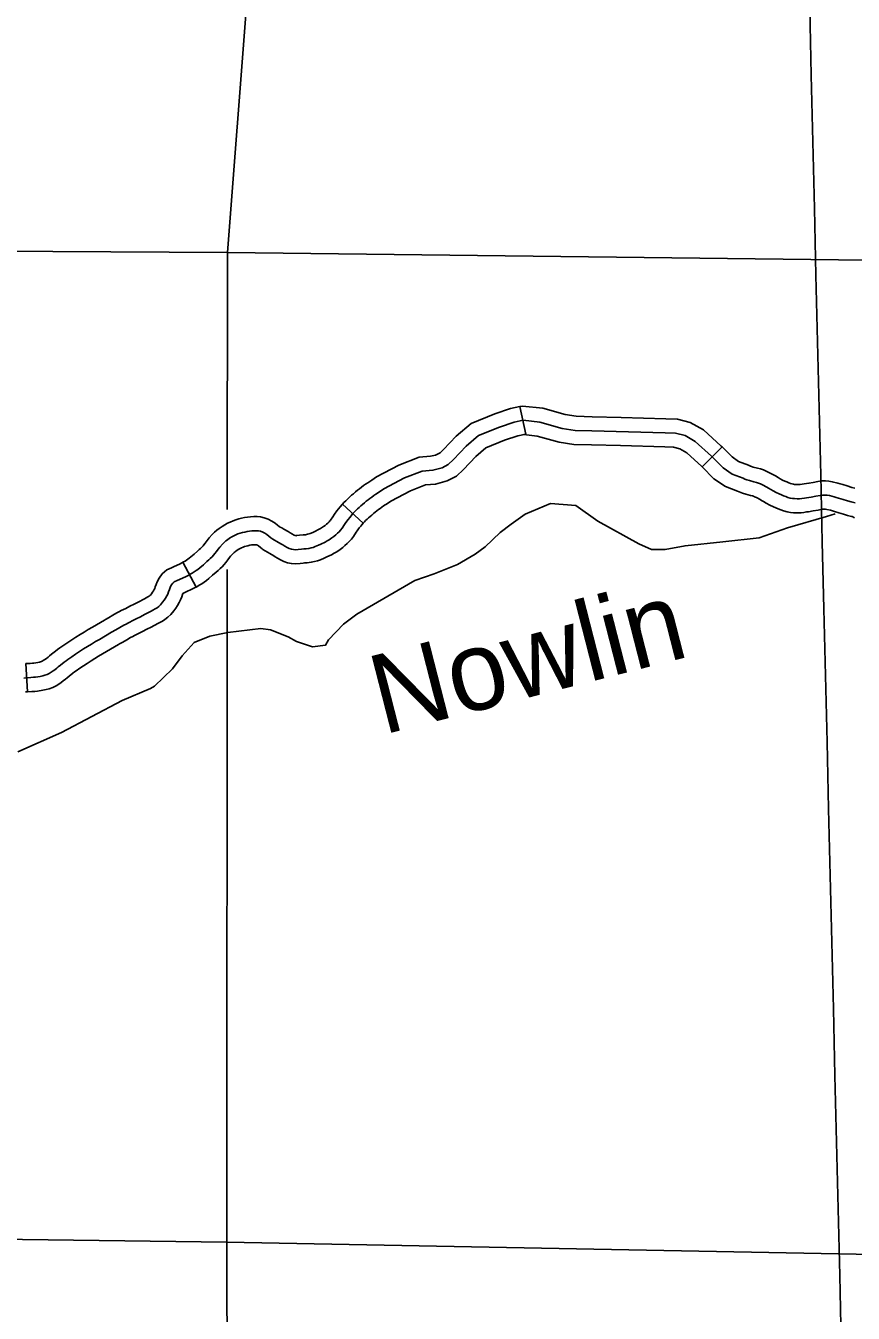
# Model space of a CAD drawing. Extents: x -19 to 366, y -4 to 359.
# Drawn here: x 134.181 to 135.016, y 195.99 to 197.29 of the extents above; entities that cross this region are included whole.
import ezdxf

# ---------------------------------------------------------------- set-up
doc = ezdxf.new("R2010")
doc.units = 0
for name, color, linetype in [('Level 35', 7, 'Continuous'), ('Level 45', 7, 'Continuous'), ('Level 5', 7, 'Continuous'), ('Level 60', 7, 'Continuous')]:
    doc.layers.add(name, color=color, linetype=linetype)

msp = doc.modelspace()

# ---------------------------------------------------------------- linework, layer by layer
at = {"layer": 'Level 35'}
for points in [[(134.5928, 196.7366), (134.6162, 196.7459), (134.6339, 196.7564), (134.644, 196.7637), (134.6594, 196.7782), (134.6702, 196.7867), (134.6845, 196.7967), (134.7101, 196.8075), (134.7355, 196.8055), (134.7579, 196.7898), (134.799, 196.7667), (134.8119, 196.7611), (134.8259, 196.7613), (134.8459, 196.7649), (134.884, 196.769), (134.9206, 196.7728), (134.9493, 196.7829), (134.9885, 196.7943)], [(134.9885, 196.7943), (134.9973, 196.7973)], [(134.1726, 196.557), (134.2167, 196.5764), (134.278, 196.6088), (134.3066, 196.6208), (134.3104, 196.6232), (134.3287, 196.6408), (134.3384, 196.6538), (134.3504, 196.6671), (134.3662, 196.6737), (134.3843, 196.6773), (134.4179, 196.6815), (134.4274, 196.68), (134.4452, 196.673), (134.4536, 196.6682), (134.4699, 196.663), (134.4831, 196.6647), (134.4861, 196.67), (134.5011, 196.6857), (134.5146, 196.6957), (134.5732, 196.73), (134.5928, 196.7366)]]:
    msp.add_lwpolyline(points, dxfattribs=at)
at = {"layer": 'Level 45'}
for p, q in [((134.6792, 196.9054), (134.6851, 196.8776)), ((134.8831, 196.8647), (134.863, 196.8446)), ((134.5002, 196.807), (134.5211, 196.7878)), ((134.3392, 196.7483), (134.3524, 196.7232)), ((134.1806, 196.6459), (134.1822, 196.6175))]:
    msp.add_line(p, q, dxfattribs=at)
for points in [[(134.6792, 196.9054), (134.6696, 196.9034), (134.6538, 196.8982), (134.63, 196.8884), (134.615, 196.8757), (134.6022, 196.862), (134.5986, 196.8587), (134.5953, 196.8569), (134.5939, 196.8565)], [(134.7814, 196.8944), (134.7522, 196.8951), (134.7361, 196.8956), (134.7247, 196.8973), (134.7022, 196.9037), (134.6818, 196.906), (134.6792, 196.9054)], [(134.9043, 196.8332), (134.8933, 196.8373), (134.8841, 196.8436), (134.8724, 196.8553), (134.856, 196.8703), (134.8458, 196.8761), (134.8361, 196.8785), (134.8259, 196.879), (134.7518, 196.8809), (134.7348, 196.8814), (134.7217, 196.8834), (134.6994, 196.8897), (134.6825, 196.8916), (134.6733, 196.8897), (134.6587, 196.8848), (134.6374, 196.8761), (134.6248, 196.8654), (134.6122, 196.8519), (134.6069, 196.847), (134.6006, 196.8436), (134.5914, 196.8412), (134.5807, 196.8402), (134.5628, 196.8334), (134.5418, 196.8223)], [(134.8831, 196.8647), (134.8823, 196.8655), (134.8644, 196.8818), (134.8511, 196.8894), (134.8382, 196.8926), (134.8265, 196.8932), (134.7814, 196.8944)], [(134.6851, 196.8776), (134.677, 196.8759), (134.6637, 196.8715), (134.6449, 196.8638), (134.6347, 196.8551), (134.6222, 196.8418), (134.6152, 196.8353), (134.6058, 196.8303), (134.6011, 196.8291)], [(134.7806, 196.866), (134.7514, 196.8668), (134.7336, 196.8673), (134.7188, 196.8695), (134.6967, 196.8757), (134.6832, 196.8772), (134.6851, 196.8776)], [(134.863, 196.8446), (134.8626, 196.845), (134.8476, 196.8587), (134.8404, 196.8628), (134.834, 196.8644), (134.8254, 196.8648), (134.7806, 196.866)], [(134.5939, 196.8565), (134.5889, 196.8552), (134.5775, 196.8542), (134.5569, 196.8464), (134.5345, 196.8345), (134.5297, 196.8313), (134.5256, 196.8286), (134.5235, 196.8271), (134.5215, 196.8256), (134.5193, 196.8241), (134.5173, 196.8225), (134.5153, 196.8209), (134.5133, 196.8192), (134.5112, 196.8175), (134.5094, 196.8159), (134.5074, 196.8142), (134.5055, 196.8124), (134.5035, 196.8104), (134.5016, 196.8085), (134.5002, 196.807)], [(134.9606, 196.8266), (134.9591, 196.8266), (134.9572, 196.8267), (134.9561, 196.8268), (134.9552, 196.827), (134.9538, 196.8274), (134.9522, 196.8279), (134.9504, 196.8286), (134.9486, 196.8293), (134.9466, 196.8302), (134.9442, 196.8313), (134.9418, 196.8326), (134.9398, 196.8338), (134.9372, 196.8354), (134.935, 196.8366), (134.9305, 196.839), (134.9277, 196.8403), (134.9249, 196.8415), (134.9219, 196.8425), (134.9188, 196.8433), (134.9144, 196.8444), (134.9129, 196.8448), (134.912, 196.8452), (134.9099, 196.8462), (134.8999, 196.85), (134.8932, 196.8546), (134.8831, 196.8647)], [(134.9629, 196.7983), (134.9621, 196.7982), (134.9586, 196.7982), (134.9553, 196.7983), (134.9522, 196.7986), (134.9488, 196.7992), (134.9453, 196.8002), (134.9426, 196.8012), (134.9399, 196.8022), (134.9375, 196.8032), (134.9349, 196.8043), (134.9315, 196.8059), (134.9277, 196.8079), (134.925, 196.8095), (134.923, 196.8107), (134.9216, 196.8115), (134.9178, 196.8136), (134.916, 196.8144), (134.9148, 196.8149), (134.9137, 196.8153), (134.9118, 196.8158), (134.907, 196.8169), (134.9037, 196.8179), (134.9005, 196.8192), (134.8986, 196.8201), (134.8867, 196.8246), (134.875, 196.8326), (134.863, 196.8446)], [(134.6011, 196.8291), (134.5939, 196.8272), (134.5839, 196.8263), (134.5687, 196.8205), (134.549, 196.81), (134.5455, 196.8077), (134.5417, 196.8051), (134.5399, 196.8039), (134.5382, 196.8026), (134.5365, 196.8014), (134.5348, 196.8001), (134.5331, 196.7988), (134.5315, 196.7974), (134.5297, 196.7959), (134.5281, 196.7945), (134.5264, 196.7931), (134.525, 196.7918), (134.5235, 196.7903), (134.5222, 196.789), (134.5211, 196.7878)], [(135.0174, 196.8083), (135.0133, 196.8093), (135.0098, 196.8103), (135.0053, 196.8117), (135.0008, 196.8131), (134.9984, 196.8138), (134.9962, 196.8144), (134.9916, 196.8155), (134.9893, 196.8159), (134.9869, 196.8161), (134.9846, 196.8161), (134.9823, 196.8158), (134.9776, 196.8149), (134.9729, 196.8141), (134.9683, 196.8134), (134.9662, 196.8131), (134.9636, 196.8127), (134.9613, 196.8124), (134.9589, 196.8124), (134.9563, 196.8125), (134.9541, 196.8127), (134.952, 196.8131), (134.9496, 196.8138), (134.9474, 196.8145), (134.9451, 196.8154), (134.943, 196.8163), (134.9408, 196.8173), (134.9378, 196.8186), (134.9348, 196.8202), (134.9324, 196.8217), (134.9301, 196.8231), (134.9283, 196.8241), (134.9241, 196.8263), (134.9218, 196.8273), (134.9198, 196.8282), (134.9178, 196.8289), (134.9153, 196.8296), (134.9107, 196.8307), (134.9083, 196.8314), (134.9062, 196.8322), (134.9043, 196.8332)], [(135.017, 196.823), (135.014, 196.8239), (135.0095, 196.8253), (135.0049, 196.8267), (135.0023, 196.8275), (134.9998, 196.8282), (134.9944, 196.8295), (134.991, 196.83), (134.9876, 196.8303), (134.9836, 196.8303), (134.9799, 196.8298), (134.9751, 196.8289), (134.9707, 196.8281), (134.9661, 196.8274), (134.964, 196.8271), (134.9617, 196.8267), (134.96, 196.8266)], [(134.5418, 196.8223), (134.5376, 196.8195), (134.5337, 196.8169), (134.5317, 196.8155), (134.5298, 196.8141), (134.5279, 196.8127), (134.526, 196.8113), (134.5242, 196.8098), (134.5224, 196.8083), (134.5204, 196.8067), (134.5188, 196.8052), (134.5169, 196.8036), (134.5152, 196.8021), (134.5135, 196.8004), (134.5119, 196.7987), (134.5104, 196.7971), (134.5088, 196.7952), (134.5074, 196.7935), (134.5058, 196.7915), (134.5035, 196.7884), (134.5022, 196.7864), (134.4997, 196.7826), (134.4983, 196.7808), (134.4968, 196.7791), (134.4951, 196.7775), (134.4933, 196.7759), (134.4915, 196.7744), (134.4894, 196.7728), (134.4867, 196.7709), (134.4848, 196.7698), (134.4826, 196.7686), (134.4783, 196.7665), (134.4761, 196.7654), (134.4727, 196.764), (134.4706, 196.7633), (134.4685, 196.7627), (134.4662, 196.7622), (134.4636, 196.7618), (134.4612, 196.7618), (134.4587, 196.7616), (134.4555, 196.7611), (134.453, 196.7608), (134.4508, 196.761), (134.4486, 196.7615), (134.4462, 196.7623), (134.4442, 196.7632), (134.4421, 196.7645), (134.4398, 196.766), (134.4381, 196.767), (134.434, 196.7693), (134.4317, 196.7706), (134.4299, 196.7717), (134.428, 196.7729), (134.426, 196.7745), (134.4238, 196.7762), (134.4217, 196.7776), (134.4197, 196.7787), (134.4174, 196.7795), (134.4153, 196.7799), (134.4133, 196.7801), (134.411, 196.7801), (134.4086, 196.78), (134.4064, 196.7797), (134.4039, 196.7793), (134.4015, 196.7788), (134.3993, 196.7783), (134.397, 196.7776), (134.3947, 196.7768), (134.3926, 196.7759), (134.3904, 196.7749), (134.3884, 196.7738), (134.3863, 196.7725), (134.3841, 196.771), (134.3825, 196.7698), (134.3809, 196.7683), (134.3791, 196.7665), (134.3765, 196.7636), (134.3748, 196.7615), (134.3731, 196.7592), (134.3715, 196.757), (134.3701, 196.7555), (134.3686, 196.7538), (134.3668, 196.7521), (134.3652, 196.7506), (134.3633, 196.7489), (134.3598, 196.7458), (134.3562, 196.7427), (134.3542, 196.7411), (134.3524, 196.7398), (134.3506, 196.7385), (134.3485, 196.7372), (134.3465, 196.7361), (134.3443, 196.735), (134.3425, 196.734), (134.3358, 196.7308), (134.3334, 196.7297), (134.3304, 196.7284), (134.3288, 196.727), (134.3274, 196.725), (134.3263, 196.7228)], [(134.5002, 196.807), (134.4997, 196.8065), (134.4978, 196.8042), (134.4962, 196.8023), (134.4945, 196.8001), (134.492, 196.7967), (134.4903, 196.7942), (134.488, 196.7907), (134.4875, 196.79), (134.4867, 196.7891), (134.4854, 196.7878), (134.484, 196.7866), (134.4826, 196.7854), (134.481, 196.7842), (134.4791, 196.7829), (134.4779, 196.7822), (134.4761, 196.7812), (134.4722, 196.7793), (134.4703, 196.7784), (134.4676, 196.7773), (134.4662, 196.7768), (134.465, 196.7765), (134.4637, 196.7762), (134.4627, 196.776), (134.4605, 196.776), (134.4568, 196.7757), (134.4537, 196.7752), (134.453, 196.7751), (134.4525, 196.7752), (134.4514, 196.7756), (134.4508, 196.7758), (134.4497, 196.7765), (134.4474, 196.778), (134.4452, 196.7793), (134.441, 196.7817), (134.4389, 196.7829), (134.4374, 196.7838), (134.4363, 196.7845), (134.4364, 196.7844)], [(135.0167, 196.7932), (135.0144, 196.7944), (135.0137, 196.7946), (135.0096, 196.7955), (135.0056, 196.7967), (135.0011, 196.7982), (134.9967, 196.7995), (134.9945, 196.8002), (134.9927, 196.8007), (134.9888, 196.8016), (134.9875, 196.8018), (134.9863, 196.8019), (134.9855, 196.8019), (134.9846, 196.8018), (134.9801, 196.8009), (134.9752, 196.8001), (134.9704, 196.7993), (134.9684, 196.799), (134.9655, 196.7986), (134.9629, 196.7983)], [(134.4364, 196.7844), (134.4347, 196.7857), (134.4322, 196.7877), (134.429, 196.7899), (134.4253, 196.7918), (134.4211, 196.7932), (134.4173, 196.794), (134.414, 196.7943), (134.4107, 196.7943), (134.4074, 196.7942), (134.4044, 196.7938), (134.4012, 196.7933), (134.3984, 196.7927), (134.3955, 196.792), (134.3926, 196.7911), (134.3897, 196.7901), (134.3868, 196.7889), (134.384, 196.7876), (134.3813, 196.7861), (134.3786, 196.7845), (134.3757, 196.7825), (134.3733, 196.7806), (134.371, 196.7785), (134.3688, 196.7763), (134.3657, 196.7728), (134.3635, 196.7701), (134.3617, 196.7676), (134.3604, 196.7659), (134.3596, 196.765), (134.3584, 196.7638), (134.357, 196.7623), (134.3556, 196.761), (134.3539, 196.7595), (134.3505, 196.7565), (134.3471, 196.7536), (134.3455, 196.7523), (134.3442, 196.7513), (134.3429, 196.7504), (134.3413, 196.7495), (134.3398, 196.7486), (134.3392, 196.7483)], [(134.5211, 196.7878), (134.521, 196.7876), (134.5197, 196.7862), (134.5186, 196.7847), (134.5171, 196.7829), (134.5151, 196.7801), (134.514, 196.7786), (134.5113, 196.7744), (134.5092, 196.7716), (134.5069, 196.7692), (134.5048, 196.7671), (134.5026, 196.7652), (134.5004, 196.7633), (134.4978, 196.7613), (134.4943, 196.7589), (134.4917, 196.7574), (134.489, 196.7559), (134.4845, 196.7537), (134.4818, 196.7524), (134.4779, 196.7508), (134.4749, 196.7497), (134.4719, 196.7489), (134.4686, 196.7482), (134.4645, 196.7476), (134.4618, 196.7476), (134.4605, 196.7475), (134.4573, 196.747), (134.4531, 196.7466), (134.4487, 196.7469), (134.4448, 196.7478), (134.4411, 196.749), (134.4377, 196.7506), (134.4345, 196.7525), (134.4323, 196.7539), (134.431, 196.7547), (134.4269, 196.757), (134.4245, 196.7584), (134.4223, 196.7597), (134.4198, 196.7613), (134.4192, 196.7618)], [(134.4192, 196.7618), (134.4173, 196.7632), (134.4154, 196.7648), (134.4144, 196.7654), (134.414, 196.7656), (134.4137, 196.7657), (134.4134, 196.7658), (134.4126, 196.7659), (134.4112, 196.7659), (134.4097, 196.7658), (134.4084, 196.7657), (134.4065, 196.7654), (134.4047, 196.765), (134.403, 196.7645), (134.4013, 196.764), (134.3998, 196.7635), (134.3984, 196.7629), (134.3969, 196.7622), (134.3954, 196.7614), (134.394, 196.7606), (134.3925, 196.7596), (134.3917, 196.7589), (134.3907, 196.758), (134.3894, 196.7567), (134.3872, 196.7543), (134.3861, 196.7529), (134.3845, 196.7507), (134.3826, 196.7481), (134.3807, 196.7459), (134.3787, 196.7438), (134.3767, 196.7419), (134.3748, 196.7401), (134.3728, 196.7383), (134.3691, 196.7351), (134.3653, 196.7318), (134.363, 196.7299), (134.3607, 196.7282), (134.3583, 196.7266), (134.3557, 196.725), (134.3533, 196.7236), (134.3524, 196.7232)], [(134.3392, 196.7483), (134.3379, 196.7476), (134.3362, 196.7468), (134.3297, 196.7436), (134.3276, 196.7426), (134.3228, 196.7406), (134.3181, 196.7365), (134.3151, 196.7322), (134.3133, 196.7286), (134.3122, 196.7257), (134.3113, 196.7233), (134.3108, 196.7219), (134.3102, 196.7209), (134.3093, 196.7193), (134.3084, 196.7179), (134.3075, 196.7165), (134.3063, 196.7151), (134.3058, 196.7146), (134.305, 196.7141), (134.3037, 196.7133), (134.302, 196.7123), (134.3004, 196.7114), (134.294, 196.7081), (134.2899, 196.706), (134.2857, 196.7039), (134.2814, 196.7017), (134.2791, 196.7005), (134.277, 196.6994), (134.2751, 196.6984), (134.2726, 196.6971), (134.2684, 196.6947), (134.2642, 196.6923), (134.2609, 196.6904)], [(134.3263, 196.7228), (134.3255, 196.7207), (134.3246, 196.7183), (134.3238, 196.7162), (134.3228, 196.7142), (134.3215, 196.712), (134.3202, 196.71), (134.3187, 196.7078), (134.3166, 196.7053), (134.3149, 196.7037), (134.313, 196.7023), (134.311, 196.7011), (134.3089, 196.6999), (134.3071, 196.6989), (134.3005, 196.6954), (134.2963, 196.6933), (134.2921, 196.6912), (134.2879, 196.6891), (134.2857, 196.6879), (134.2837, 196.6869), (134.2819, 196.6859), (134.2795, 196.6846), (134.2754, 196.6823), (134.2713, 196.68), (134.2672, 196.6776), (134.255, 196.6704), (134.2509, 196.6681), (134.2468, 196.6656), (134.2428, 196.6632), (134.2388, 196.6607), (134.2348, 196.6581), (134.2308, 196.6555), (134.2269, 196.6529), (134.2231, 196.6502), (134.2213, 196.6489), (134.2193, 196.6473), (134.2156, 196.6443), (134.2134, 196.6426), (134.2119, 196.6414), (134.2099, 196.6398), (134.2081, 196.6385), (134.2061, 196.6372), (134.2042, 196.636), (134.2022, 196.6349), (134.1999, 196.6341), (134.1978, 196.6335), (134.1952, 196.633), (134.1905, 196.6323), (134.1884, 196.6321), (134.1858, 196.6319), (134.1811, 196.6317), (134.1786, 196.6314)], [(134.3524, 196.7232), (134.3508, 196.7223), (134.3488, 196.7213), (134.3419, 196.718), (134.3392, 196.7167), (134.3391, 196.7167), (134.3388, 196.7157), (134.3379, 196.7133), (134.3368, 196.7104), (134.3353, 196.7075), (134.3337, 196.7046), (134.332, 196.702), (134.33, 196.6992), (134.3269, 196.6955), (134.3239, 196.6927), (134.3209, 196.6905), (134.3184, 196.6889), (134.3158, 196.6875), (134.3138, 196.6863), (134.307, 196.6828), (134.3027, 196.6806), (134.2985, 196.6785), (134.2943, 196.6764), (134.2922, 196.6753), (134.2903, 196.6743), (134.2886, 196.6734), (134.2864, 196.6722), (134.2824, 196.67), (134.2784, 196.6677), (134.2752, 196.6658)], [(134.2609, 196.6904), (134.2601, 196.6899), (134.2478, 196.6827), (134.2437, 196.6803), (134.2395, 196.6778), (134.2353, 196.6753), (134.2312, 196.6727), (134.227, 196.67), (134.2229, 196.6673), (134.2189, 196.6646), (134.2148, 196.6617), (134.2127, 196.6602), (134.2105, 196.6585), (134.2067, 196.6554), (134.2046, 196.6537), (134.2031, 196.6526), (134.2014, 196.6512), (134.1999, 196.6501), (134.1983, 196.649), (134.1971, 196.6483), (134.1964, 196.648), (134.1956, 196.6477), (134.1946, 196.6474), (134.1927, 196.647), (134.1888, 196.6464), (134.1873, 196.6463), (134.1849, 196.6461), (134.1806, 196.6459)], [(134.2752, 196.6658), (134.2743, 196.6653), (134.2621, 196.6582), (134.2581, 196.6558), (134.2541, 196.6535), (134.2502, 196.6511), (134.2464, 196.6487), (134.2425, 196.6462), (134.2387, 196.6437), (134.235, 196.6412), (134.2313, 196.6386), (134.2298, 196.6375), (134.2281, 196.6362), (134.2245, 196.6333), (134.2223, 196.6315), (134.2206, 196.6302), (134.2184, 196.6285), (134.2163, 196.6269), (134.2139, 196.6253), (134.2112, 196.6236), (134.2079, 196.6219), (134.2041, 196.6205), (134.201, 196.6197), (134.1977, 196.619), (134.1923, 196.6182), (134.1896, 196.6179), (134.1867, 196.6178), (134.1822, 196.6175)], [(134.1822, 196.6175), (134.1822, 196.6175), (134.1804, 196.6173)]]:
    msp.add_lwpolyline(points, dxfattribs=at)
at = {"layer": 'Level 5'}
for points in [[(134.4615, 198.0663), (134.3841, 197.0611)], [(134.3841, 197.0611), (133.6196, 197.0653)], [(134.3841, 197.0611), (134.3839, 196.8016)], [(135.3933, 197.049), (134.3841, 197.0611)], [(134.3839, 196.7408), (134.3834, 196.0617)], [(133.4555, 196.0738), (134.3834, 196.0617)], [(134.3834, 196.0617), (135.2832, 196.0448)], [(134.3834, 196.0617), (134.3847, 195.4655)]]:
    msp.add_lwpolyline(points, dxfattribs=at)
at = {"layer": 'Level 60'}
for points in [[(139.4406, 1.5315), (139.2511, 10.1473), (139.0608, 18.7633), (138.8699, 27.3793), (138.6784, 35.9956), (138.4861, 44.6119), (138.2932, 53.2285), (138.0997, 61.8451), (137.9055, 70.4619), (137.7106, 79.0789), (137.5151, 87.6959), (137.319, 96.3132), (137.1221, 104.9306), (136.9247, 113.5481), (136.7265, 122.1658), (136.5278, 130.7836), (136.3283, 139.4016), (136.1282, 148.0197), (135.9275, 156.6379), (135.7261, 165.2564), (135.5241, 173.8749), (135.3214, 182.4936), (135.1181, 191.1125), (134.9141, 199.7315), (134.7095, 208.3506), (134.5043, 216.9699), (134.2984, 225.5894), (134.0919, 234.209), (133.8847, 242.8288), (133.6769, 251.4487), (133.4685, 260.0687), (133.2594, 268.6889), (133.0497, 277.3093), (132.8393, 285.9298), (132.6283, 294.5504), (132.4167, 303.1713), (132.2044, 311.7922), (131.9916, 320.4133), (131.778, 329.0346), (131.5639, 337.656), (131.3491, 346.2776)], [(0, 189.5162), (7.1121, 189.5206), (14.2243, 189.5339), (21.3364, 189.556), (28.4484, 189.5869), (35.5605, 189.6267), (42.6725, 189.6754), (49.7844, 189.7329), (56.8962, 189.7992), (64.0079, 189.8744), (71.1196, 189.9584), (78.2311, 190.0512), (85.3425, 190.1529), (92.4538, 190.2635), (99.5649, 190.3829), (106.6759, 190.5111), (113.7867, 190.6482), (120.8974, 190.7941), (128.0078, 190.9489), (135.1181, 191.1125), (142.2282, 191.2849), (149.338, 191.4662), (156.4476, 191.6563), (163.5569, 191.8553), (170.666, 192.0631), (177.7749, 192.2798), (184.8835, 192.5053), (191.9917, 192.7396), (199.0997, 192.9828), (206.2074, 193.2348), (213.3147, 193.4956), (220.4218, 193.7653), (227.5285, 194.0438), (234.6348, 194.3312), (241.7408, 194.6274), (248.8464, 194.9324), (255.9516, 195.2463), (263.0564, 195.569), (270.1608, 195.9005), (277.2648, 196.2409), (284.3683, 196.5901), (291.4715, 196.9481), (298.5741, 197.315), (305.6763, 197.6907), (312.7781, 198.0753), (319.8793, 198.4686), (326.9801, 198.8708), (334.0804, 199.2818), (341.1801, 199.7017)]]:
    msp.add_spline(points, degree=3, dxfattribs=at)

# ---------------------------------------------------------------- texts
at = {"layer": 'Level 35'}
msp.add_text('Nowlin', height=0.08, rotation=14.3627, dxfattribs=at).set_placement((134.5409, 196.5739))

doc.saveas('drawing.dxf')
